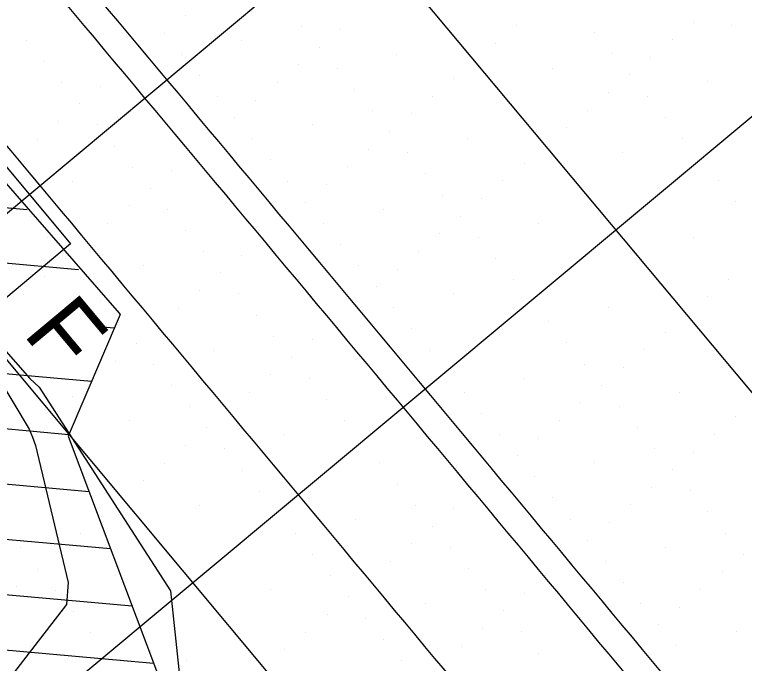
# Model space of a CAD drawing. Extents: x 2042995 to 2043795, y 305365 to 306249.
# Drawn here: x 2043306.13 to 2043332.63, y 305794.72 to 305818.29 of the extents above; entities that cross this region are included whole.
import ezdxf

# ---------------------------------------------------------------- set-up
doc = ezdxf.new("R2010")
doc.units = 0
for name, color, linetype in [('BR_CENTER LINES', 7, 'Continuous'), ('BR_CONCRETE', 7, 'Continuous'), ('BR_EXIST_GROUND_CL', 7, 'Continuous'), ('BR_EXIST_GROUND_LT', 7, 'Continuous'), ('BR_EXIST_GROUND_RT', 7, 'Continuous'), ('BR_GRID DOTS', 7, 'Continuous'), ('BR_GRID LINES', 7, 'Continuous'), ('BR_PRESTRESSED BEAM', 7, 'Continuous'), ('BR_TABLE LINES', 7, 'Continuous'), ('BR_TEXT', 7, 'Continuous')]:
    doc.layers.add(name, color=color, linetype=linetype)

msp = doc.modelspace()

# ---------------------------------------------------------------- linework, layer by layer
at = {"layer": 'BR_CENTER LINES'}
msp.add_line((2043349.78, 305847.751), (2043253.934, 305767.702), dxfattribs=at)
at = {"layer": 'BR_CONCRETE'}
for p, q in [((2043305.18, 305813.536), (2043308.166, 305809.961)), ((2043308.166, 305809.961), (2043304.328, 305806.756))]:
    msp.add_line(p, q, dxfattribs=at)
for points in [[(2043139.109, 306017.548), (2043148.199, 306007.16), (2043160.233, 305993.368), (2043172.245, 305979.557), (2043184.234, 305965.727), (2043196.201, 305951.879), (2043208.145, 305938.012), (2043220.067, 305924.126), (2043231.966, 305910.221), (2043243.843, 305896.297), (2043255.698, 305882.355), (2043267.529, 305868.394), (2043279.339, 305854.414), (2043291.126, 305840.415), (2043302.89, 305826.398), (2043314.632, 305812.361), (2043326.352, 305798.306), (2043338.049, 305784.233), (2043349.724, 305770.14), (2043361.376, 305756.029), (2043373.005, 305741.899), (2043384.613, 305727.75), (2043396.197, 305713.582), (2043407.76, 305699.396), (2043419.299, 305685.191), (2043430.817, 305670.967), (2043442.311, 305656.724), (2043453.784, 305642.463), (2043465.234, 305628.182), (2043476.661, 305613.883), (2043488.066, 305599.566), (2043499.448, 305585.229), (2043510.808, 305570.874), (2043522.146, 305556.5), (2043533.461, 305542.107), (2043544.753, 305527.695), (2043547.219, 305524.543)], [(2043273.14, 305860.139), (2043278.86, 305853.362), (2043290.647, 305839.364), (2043302.411, 305825.346), (2043314.153, 305811.31), (2043325.873, 305797.255), (2043337.57, 305783.181), (2043349.245, 305769.089), (2043360.897, 305754.977), (2043372.526, 305740.847), (2043384.134, 305726.698), (2043395.718, 305712.531), (2043407.281, 305698.344), (2043418.82, 305684.139), (2043425.623, 305675.744)]]:
    msp.add_spline(points, degree=3, dxfattribs=at)
at = {"layer": 'BR_EXIST_GROUND_CL'}
msp.add_lwpolyline([(2043255.733, 305870.455), (2043271.607, 305852.06), (2043272.069, 305851.528), (2043287.883, 305833.202), (2043288.154, 305832.889), (2043288.628, 305832.326), (2043304.346, 305813.856), (2043304.811, 305813.309), (2043304.895, 305813.213), (2043309.929, 305807.442), (2043309.959, 305807.409), (2043309.971, 305807.394), (2043309.925, 305807.313), (2043308.08, 305802.975), (2043311.357, 305794.254)], dxfattribs=at)
at = {"layer": 'BR_EXIST_GROUND_LT'}
msp.add_lwpolyline([(2043275.475, 305840.619), (2043283.608, 305831.48), (2043289.459, 305825.521), (2043297.05, 305817.91), (2043299.395, 305815.12), (2043301.853, 305811.191), (2043301.873, 305811.167), (2043301.978, 305810.973), (2043304.949, 305806.086), (2043306.658, 305803.234), (2043306.78, 305802.94), (2043306.898, 305802.631), (2043308.075, 305797.659), (2043308.018, 305796.863), (2043306.871, 305795.372), (2043298.097, 305784.008)], dxfattribs=at)
at = {"layer": 'BR_EXIST_GROUND_RT'}
msp.add_lwpolyline([(2043274.94, 305840.335), (2043284.934, 305828.894), (2043285.055, 305828.756), (2043290.883, 305822.399), (2043296.235, 305816.825), (2043301.394, 305810.974), (2043302.341, 305810.012), (2043306.685, 305805.076), (2043307.028, 305804.753), (2043311.795, 305797.361), (2043312.912, 305786.83)], dxfattribs=at)
at = {"layer": 'BR_GRID DOTS'}
for p, q in [((2043312.33, 305818.256), (2043312.33, 305818.256)), ((2043308.745, 305817.868), (2043308.745, 305817.868)), ((2043316.556, 305817.876), (2043316.556, 305817.876)), ((2043324.366, 305817.885), (2043324.366, 305817.885)), ((2043330.767, 305818.02), (2043330.767, 305818.02)), ((2043332.176, 305817.893), (2043332.176, 305817.893)), ((2043311.562, 305817.615), (2043311.562, 305817.615)), ((2043317.964, 305817.75), (2043317.964, 305817.75)), ((2043327.183, 305817.632), (2043327.183, 305817.632)), ((2043306.569, 305817.353), (2043306.569, 305817.353)), ((2043314.379, 305817.362), (2043314.379, 305817.362)), ((2043330, 305817.379), (2043330, 305817.379)), ((2043317.197, 305817.109), (2043317.197, 305817.109)), ((2043323.598, 305817.244), (2043323.598, 305817.244)), ((2043310.795, 305816.974), (2043310.795, 305816.974)), ((2043312.203, 305816.847), (2043312.203, 305816.847)), ((2043320.014, 305816.856), (2043320.014, 305816.856)), ((2043327.824, 305816.864), (2043327.824, 305816.864)), ((2043307.21, 305816.585), (2043307.21, 305816.585)), ((2043322.831, 305816.603), (2043322.831, 305816.603)), ((2043329.232, 305816.738), (2043329.232, 305816.738)), ((2043310.027, 305816.333), (2043310.027, 305816.333)), ((2043316.429, 305816.468), (2043316.429, 305816.468)), ((2043317.838, 305816.341), (2043317.838, 305816.341)), ((2043325.648, 305816.35), (2043325.648, 305816.35)), ((2043312.844, 305816.08), (2043312.844, 305816.08)), ((2043328.465, 305816.097), (2043328.465, 305816.097)), ((2043307.851, 305815.818), (2043307.851, 305815.818)), ((2043315.662, 305815.827), (2043315.662, 305815.827)), ((2043322.063, 305815.962), (2043322.063, 305815.962)), ((2043331.282, 305815.844), (2043331.282, 305815.844)), ((2043309.26, 305815.691), (2043309.26, 305815.691)), ((2043318.479, 305815.574), (2043318.479, 305815.574)), ((2043313.485, 305815.312), (2043313.485, 305815.312)), ((2043321.296, 305815.321), (2043321.296, 305815.321)), ((2043327.697, 305815.456), (2043327.697, 305815.456)), ((2043329.106, 305815.329), (2043329.106, 305815.329)), ((2043308.492, 305815.05), (2043308.492, 305815.05)), ((2043314.894, 305815.186), (2043314.894, 305815.186)), ((2043311.309, 305814.797), (2043311.309, 305814.797)), ((2043319.12, 305814.806), (2043319.12, 305814.806)), ((2043320.528, 305814.68), (2043320.528, 305814.68)), ((2043326.93, 305814.815), (2043326.93, 305814.815)), ((2043307.725, 305814.409), (2043307.725, 305814.409)), ((2043314.127, 305814.544), (2043314.127, 305814.544)), ((2043329.747, 305814.562), (2043329.747, 305814.562)), ((2043309.133, 305814.283), (2043309.133, 305814.283)), ((2043316.944, 305814.291), (2043316.944, 305814.291)), ((2043326.162, 305814.174), (2043326.162, 305814.174)), ((2043313.359, 305813.903), (2043313.359, 305813.903)), ((2043319.761, 305814.039), (2043319.761, 305814.039)), ((2043306.957, 305813.768), (2043306.957, 305813.768)), ((2043314.768, 305813.777), (2043314.768, 305813.777)), ((2043322.578, 305813.786), (2043322.578, 305813.786)), ((2043330.388, 305813.794), (2043330.388, 305813.794)), ((2043309.774, 305813.515), (2043309.774, 305813.515)), ((2043318.993, 305813.397), (2043318.993, 305813.397)), ((2043325.395, 305813.533), (2043325.395, 305813.533)), ((2043306.19, 305813.127), (2043306.19, 305813.127)), ((2043312.591, 305813.262), (2043312.591, 305813.262)), ((2043320.402, 305813.271), (2043320.402, 305813.271)), ((2043328.212, 305813.28), (2043328.212, 305813.28)), ((2043315.409, 305813.009), (2043315.409, 305813.009)), ((2043324.627, 305812.892), (2043324.627, 305812.892)), ((2043310.415, 305812.748), (2043310.415, 305812.748)), ((2043311.824, 305812.621), (2043311.824, 305812.621)), ((2043318.226, 305812.756), (2043318.226, 305812.756)), ((2043321.043, 305812.503), (2043321.043, 305812.503)), ((2043308.239, 305812.233), (2043308.239, 305812.233)), ((2043316.05, 305812.242), (2043316.05, 305812.242)), ((2043317.458, 305812.115), (2043317.458, 305812.115)), ((2043323.86, 305812.25), (2043323.86, 305812.25)), ((2043331.67, 305812.259), (2043331.67, 305812.259)), ((2043311.056, 305811.98), (2043311.056, 305811.98)), ((2043313.874, 305811.727), (2043313.874, 305811.727)), ((2043321.684, 305811.736), (2043321.684, 305811.736)), ((2043323.092, 305811.609), (2043323.092, 305811.609)), ((2043310.289, 305811.339), (2043310.289, 305811.339)), ((2043316.691, 305811.474), (2043316.691, 305811.474)), ((2043332.311, 305811.492), (2043332.311, 305811.492)), ((2043311.697, 305811.213), (2043311.697, 305811.213)), ((2043319.508, 305811.221), (2043319.508, 305811.221)), ((2043322.325, 305810.968), (2043322.325, 305810.968)), ((2043306.704, 305810.951), (2043306.704, 305810.951)), ((2043315.923, 305810.833), (2043315.923, 305810.833)), ((2043317.332, 305810.707), (2043317.332, 305810.707)), ((2043325.142, 305810.715), (2043325.142, 305810.715)), ((2043309.521, 305810.698), (2043309.521, 305810.698)), ((2043312.338, 305810.445), (2043312.338, 305810.445)), ((2043307.345, 305810.184), (2043307.345, 305810.184)), ((2043315.156, 305810.192), (2043315.156, 305810.192)), ((2043321.557, 305810.327), (2043321.557, 305810.327)), ((2043322.966, 305810.201), (2043322.966, 305810.201)), ((2043330.776, 305810.209), (2043330.776, 305810.209)), ((2043308.754, 305810.057), (2043308.754, 305810.057)), ((2043317.973, 305809.939), (2043317.973, 305809.939)), ((2043312.98, 305809.678), (2043312.98, 305809.678)), ((2043320.79, 305809.686), (2043320.79, 305809.686)), ((2043307.986, 305809.416), (2043307.986, 305809.416)), ((2043314.388, 305809.551), (2043314.388, 305809.551)), ((2043323.607, 305809.433), (2043323.607, 305809.433)), ((2043310.803, 305809.163), (2043310.803, 305809.163)), ((2043318.614, 305809.172), (2043318.614, 305809.172)), ((2043313.621, 305808.91), (2043313.621, 305808.91)), ((2043320.022, 305809.045), (2043320.022, 305809.045)), ((2043307.219, 305808.775), (2043307.219, 305808.775)), ((2043308.627, 305808.649), (2043308.627, 305808.649)), ((2043316.438, 305808.657), (2043316.438, 305808.657)), ((2043324.248, 305808.666), (2043324.248, 305808.666)), ((2043332.058, 305808.674), (2043332.058, 305808.674)), ((2043319.255, 305808.404), (2043319.255, 305808.404)), ((2043306.451, 305808.134), (2043306.451, 305808.134)), ((2043312.853, 305808.269), (2043312.853, 305808.269)), ((2043314.262, 305808.143), (2043314.262, 305808.143)), ((2043322.072, 305808.151), (2043322.072, 305808.151)), ((2043309.268, 305807.881), (2043309.268, 305807.881)), ((2043331.291, 305808.033), (2043331.291, 305808.033)), ((2043312.085, 305807.628), (2043312.085, 305807.628)), ((2043318.487, 305807.763), (2043318.487, 305807.763)), ((2043319.896, 305807.637), (2043319.896, 305807.637)), ((2043327.706, 305807.645), (2043327.706, 305807.645)), ((2043314.903, 305807.375), (2043314.903, 305807.375)), ((2043330.523, 305807.392), (2043330.523, 305807.392)), ((2043309.909, 305807.114), (2043309.909, 305807.114)), ((2043317.72, 305807.122), (2043317.72, 305807.122)), ((2043325.53, 305807.131), (2043325.53, 305807.131)), ((2043311.318, 305806.987), (2043311.318, 305806.987)), ((2043320.537, 305806.869), (2043320.537, 305806.869)), ((2043329.756, 305806.751), (2043329.756, 305806.751)), ((2043307.733, 305806.599), (2043307.733, 305806.599)), ((2043315.544, 305806.608), (2043315.544, 305806.608)), ((2043316.952, 305806.481), (2043316.952, 305806.481)), ((2043310.55, 305806.346), (2043310.55, 305806.346)), ((2043326.171, 305806.363), (2043326.171, 305806.363)), ((2043313.368, 305806.093), (2043313.368, 305806.093)), ((2043321.178, 305806.102), (2043321.178, 305806.102)), ((2043328.988, 305806.11), (2043328.988, 305806.11)), ((2043309.783, 305805.705), (2043309.783, 305805.705)), ((2043316.185, 305805.84), (2043316.185, 305805.84)), ((2043311.191, 305805.579), (2043311.191, 305805.579)), ((2043319.002, 305805.587), (2043319.002, 305805.587)), ((2043326.812, 305805.596), (2043326.812, 305805.596)), ((2043328.221, 305805.469), (2043328.221, 305805.469)), ((2043315.417, 305805.199), (2043315.417, 305805.199)), ((2043309.015, 305805.064), (2043309.015, 305805.064)), ((2043316.826, 305805.073), (2043316.826, 305805.073)), ((2043324.636, 305805.081), (2043324.636, 305805.081)), ((2043311.833, 305804.811), (2043311.833, 305804.811)), ((2043327.453, 305804.828), (2043327.453, 305804.828)), ((2043308.248, 305804.423), (2043308.248, 305804.423)), ((2043314.65, 305804.558), (2043314.65, 305804.558)), ((2043322.46, 305804.567), (2043322.46, 305804.567)), ((2043330.27, 305804.575), (2043330.27, 305804.575)), ((2043317.467, 305804.305), (2043317.467, 305804.305)), ((2043326.685, 305804.187), (2043326.685, 305804.187)), ((2043312.474, 305804.044), (2043312.474, 305804.044)), ((2043313.882, 305803.917), (2043313.882, 305803.917)), ((2043328.094, 305804.061), (2043328.094, 305804.061)), ((2043307.48, 305803.782), (2043307.48, 305803.782)), ((2043323.101, 305803.799), (2043323.101, 305803.799)), ((2043325.918, 305803.546), (2043325.918, 305803.546)), ((2043332.32, 305803.681), (2043332.32, 305803.681)), ((2043310.297, 305803.529), (2043310.297, 305803.529)), ((2043318.108, 305803.538), (2043318.108, 305803.538)), ((2043328.735, 305803.293), (2043328.735, 305803.293)), ((2043306.713, 305803.141), (2043306.713, 305803.141)), ((2043313.115, 305803.276), (2043313.115, 305803.276)), ((2043315.932, 305803.023), (2043315.932, 305803.023)), ((2043323.742, 305803.032), (2043323.742, 305803.032)), ((2043331.552, 305803.04), (2043331.552, 305803.04)), ((2043325.15, 305802.905), (2043325.15, 305802.905)), ((2043312.347, 305802.635), (2043312.347, 305802.635)), ((2043313.756, 305802.509), (2043313.756, 305802.509)), ((2043321.566, 305802.517), (2043321.566, 305802.517)), ((2043329.376, 305802.526), (2043329.376, 305802.526)), ((2043324.383, 305802.264), (2043324.383, 305802.264)), ((2043330.785, 305802.399), (2043330.785, 305802.399)), ((2043311.58, 305801.994), (2043311.58, 305801.994)), ((2043319.39, 305802.003), (2043319.39, 305802.003)), ((2043327.2, 305802.011), (2043327.2, 305802.011)), ((2043314.397, 305801.741), (2043314.397, 305801.741)), ((2043330.017, 305801.758), (2043330.017, 305801.758)), ((2043323.615, 305801.623), (2043323.615, 305801.623)), ((2043325.024, 305801.497), (2043325.024, 305801.497)), ((2043310.812, 305801.353), (2043310.812, 305801.353)), ((2043320.031, 305801.235), (2043320.031, 305801.235)), ((2043307.227, 305800.965), (2043307.227, 305800.965)), ((2043315.038, 305800.974), (2043315.038, 305800.974)), ((2043322.848, 305800.982), (2043322.848, 305800.982)), ((2043329.25, 305801.117), (2043329.25, 305801.117)), ((2043330.658, 305800.991), (2043330.658, 305800.991)), ((2043310.044, 305800.712), (2043310.044, 305800.712)), ((2043325.665, 305800.729), (2043325.665, 305800.729)), ((2043312.862, 305800.459), (2043312.862, 305800.459)), ((2043320.672, 305800.468), (2043320.672, 305800.468)), ((2043328.482, 305800.476), (2043328.482, 305800.476)), ((2043322.08, 305800.341), (2043322.08, 305800.341)), ((2043331.299, 305800.223), (2043331.299, 305800.223)), ((2043309.277, 305800.071), (2043309.277, 305800.071)), ((2043318.496, 305799.953), (2043318.496, 305799.953)), ((2043326.306, 305799.962), (2043326.306, 305799.962)), ((2043321.313, 305799.7), (2043321.313, 305799.7)), ((2043327.715, 305799.835), (2043327.715, 305799.835)), ((2043308.509, 305799.43), (2043308.509, 305799.43)), ((2043316.32, 305799.439), (2043316.32, 305799.439)), ((2043324.13, 305799.447), (2043324.13, 305799.447)), ((2043331.94, 305799.456), (2043331.94, 305799.456)), ((2043320.545, 305799.059), (2043320.545, 305799.059)), ((2043326.947, 305799.194), (2043326.947, 305799.194)), ((2043306.333, 305798.915), (2043306.333, 305798.915)), ((2043307.742, 305798.789), (2043307.742, 305798.789)), ((2043321.954, 305798.933), (2043321.954, 305798.933)), ((2043329.764, 305798.941), (2043329.764, 305798.941)), ((2043316.961, 305798.671), (2043316.961, 305798.671)), ((2043326.18, 305798.553), (2043326.18, 305798.553)), ((2043332.581, 305798.688), (2043332.581, 305798.688)), ((2043319.778, 305798.418), (2043319.778, 305798.418)), ((2043327.588, 305798.427), (2043327.588, 305798.427)), ((2043306.974, 305798.148), (2043306.974, 305798.148)), ((2043322.595, 305798.165), (2043322.595, 305798.165)), ((2043331.814, 305798.047), (2043331.814, 305798.047)), ((2043309.791, 305797.895), (2043309.791, 305797.895)), ((2043317.602, 305797.903), (2043317.602, 305797.903)), ((2043319.01, 305797.777), (2043319.01, 305797.777)), ((2043325.412, 305797.912), (2043325.412, 305797.912)), ((2043306.207, 305797.507), (2043306.207, 305797.507)), ((2043328.229, 305797.659), (2043328.229, 305797.659)), ((2043307.615, 305797.38), (2043307.615, 305797.38)), ((2043315.426, 305797.389), (2043315.426, 305797.389)), ((2043323.236, 305797.398), (2043323.236, 305797.398)), ((2043324.644, 305797.271), (2043324.644, 305797.271)), ((2043331.046, 305797.406), (2043331.046, 305797.406)), ((2043318.243, 305797.136), (2043318.243, 305797.136)), ((2043321.06, 305796.883), (2043321.06, 305796.883)), ((2043328.87, 305796.892), (2043328.87, 305796.892)), ((2043330.279, 305796.765), (2043330.279, 305796.765)), ((2043308.256, 305796.613), (2043308.256, 305796.613)), ((2043317.475, 305796.495), (2043317.475, 305796.495)), ((2043323.877, 305796.63), (2043323.877, 305796.63)), ((2043318.884, 305796.368), (2043318.884, 305796.368)), ((2043326.694, 305796.377), (2043326.694, 305796.377)), ((2043323.109, 305795.989), (2043323.109, 305795.989)), ((2043324.518, 305795.862), (2043324.518, 305795.862)), ((2043329.511, 305796.124), (2043329.511, 305796.124)), ((2043332.328, 305795.871), (2043332.328, 305795.871)), ((2043308.897, 305795.845), (2043308.897, 305795.845)), ((2043316.708, 305795.854), (2043316.708, 305795.854)), ((2043319.525, 305795.601), (2043319.525, 305795.601)), ((2043322.342, 305795.348), (2043322.342, 305795.348)), ((2043328.744, 305795.483), (2043328.744, 305795.483)), ((2043330.152, 305795.357), (2043330.152, 305795.357)), ((2043306.721, 305795.331), (2043306.721, 305795.331)), ((2043315.94, 305795.213), (2043315.94, 305795.213)), ((2043325.159, 305795.095), (2043325.159, 305795.095)), ((2043312.356, 305794.825), (2043312.356, 305794.825)), ((2043320.166, 305794.833), (2043320.166, 305794.833)), ((2043327.976, 305794.842), (2043327.976, 305794.842))]:
    msp.add_line(p, q, dxfattribs=at)
at = {"layer": 'BR_GRID LINES'}
for p, q in [((2043137.788, 306038.16), (2043569.411, 305521.364)), ((2043122.438, 306025.339), (2043554.061, 305508.544)), ((2043374.01, 305848.924), (2043220.506, 305720.719))]:
    msp.add_line(p, q, dxfattribs=at)
at = {"layer": 'BR_PRESTRESSED BEAM'}
msp.add_spline([(2043269.336, 305856.962), (2043274.734, 305850.568), (2043286.521, 305836.569), (2043298.285, 305822.551), (2043310.027, 305808.515), (2043321.747, 305794.46), (2043333.444, 305780.386), (2043345.119, 305766.294), (2043356.771, 305752.183), (2043368.4, 305738.053), (2043380.007, 305723.904), (2043391.592, 305709.736), (2043403.154, 305695.55), (2043414.694, 305681.345), (2043421.811, 305672.561)], degree=3, dxfattribs=at)
at = {"layer": 'BR_TABLE LINES'}
for p, q in [((2043282.366, 305813.383), (2043306.588, 305811.208)), ((2043282.882, 305811.329), (2043308.452, 305809.032)), ((2043283.913, 305807.22), (2043308.93, 305804.973)), ((2043309.325, 305806.946), (2043309.753, 305806.907)), ((2043282.218, 305805.364), (2043308.108, 305803.039)), ((2043281.966, 305803.379), (2043308.835, 305800.966)), ((2043283.78, 305801.208), (2043309.616, 305798.888)), ((2043285.593, 305799.037), (2043310.397, 305796.809)), ((2043287.406, 305796.866), (2043311.178, 305794.731))]:
    msp.add_line(p, q, dxfattribs=at)

# ---------------------------------------------------------------- texts
at = {"layer": 'BR_TEXT'}
msp.add_text('F', height=2.5, rotation=309.8684, dxfattribs=at).set_placement((2043306.395, 305806.694))

doc.saveas('drawing.dxf')
